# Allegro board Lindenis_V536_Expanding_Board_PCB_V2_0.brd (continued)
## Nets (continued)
MICIN1P: C52.2 U901.89(MICIN1P)
MICRO-USB0-DM: D25.1(ANODE) U51.6(HSD1-) USB1.2(D-)
MICRO-USB0-DP: D26.1(ANODE) U51.7(HSD1+) USB1.3(D+)
MIPI-DSI-CKN: J7.9(CLKN) TP56.1(TP) U901.143(MIPI_DSI_CKN)
MIPI-DSI-CKP: J7.8(CLKP) TP57.1(TP) U901.142(MIPI_DSI_CKP)
MIPI-DSI-D0N: J7.3(D0N) TP52.1(TP) U901.137(MIPI_DSI_D0N)
MIPI-DSI-D0P: J7.2(D0P) TP53.1(TP) U901.136(MIPI_DSI_D0P)
MIPI-DSI-D1N: J7.6(D1N) TP54.1(TP) U901.139(MIPI_DSI_D1N)
MIPI-DSI-D1P: J7.5(D1P) TP55.1(TP) U901.138(MIPI_DSI_D1P)
MIPI-DSI-D2N: J7.12(D2N) TP58.1(TP) U901.141(MIPI_DSI_D2N)
MIPI-DSI-D2P: J7.11(D2P) TP59.1(TP) U901.140(MIPI_DSI_D2P)
MIPI-DSI-D3N: J7.15(D3N) TP60.1(TP) U901.145(MIPI_DSI_D3N)
MIPI-DSI-D3P: J7.14(D3P) TP61.1(TP) U901.144(MIPI_DSI_D3P)
NALE-EMMC-RST: U901.77(EMMC_RST) UM2.12
NDQ0-EMMC-D7: U901.86(EMMC_D7) UM2.31
NDQ1-EMMC-D2: U901.84(EMMC_D2) UM2.27
NDQ2-EMMC-D6: U901.83(EMMC_D6) UM2.33
NDQ3-EMMC-D1: U901.81(EMMC_D1) UM2.29
NDQ4-EMMC-D5: U901.82(EMMC_D5) UM2.2
NDQ5-EMMC-D0: U901.85(EMMC_D0) UM2.6
NDQ6-EMMC-D4: U901.79(EMMC_D4) UM2.4
NDQ7-EMMC-D3: U901.80(EMMC_D3) UM2.10
NRB0-EMMC-CMD: U901.75(EMMC_CMD) UM2.25
NRE: RM50.2 UM2.8
NRE-EMMC-CLK: RM50.1 U901.76(EMMC_CLK)
NWE-EMMC-DS: U901.78(EMMC_DS) UM2.15
OVCUR1#: R237.2 R263.1 U32.21(OVCUR1#)
PA-SHDN: R182.2 U901.53(PA_SHDN)
PH4: J56.1 RU13.1 U901.56(PH4) UU3.4(EN)
PH10: J56.2 R549.2 U901.52(PH10)
PHYRST: CM14.1 Q23.3(D) RM21.1 RM45.2 UM1.12(PHYRSTB)
PHYRSTB: Q23.2(S) RM45.1 U901.16(RGMII_RESET)
PS: C291.2 C294.2 J11.2 J11.4 L12.1 U39.6(VIN) U901.35(PS1) U901.36(PS2)
PWKEY: CL67.1 DL52.2(CATHODE) QL13.3(C) U27.3(PWKEY)
PWR-LED: RL6.2 RL56.2 RL57.2 U901.55(LED_PWR)
PWRON: CK15.1 RP62.2 U901.7(PWRON)
REGOUT: CM17.2 LM1.1 RM42.2 UM1.30(REG_OUT)
RF-IN: RG3.1 U8.11(RF_IN)
RGMII-CLKIN-125M: R436.1 R541.1 U901.17(RGMII_CLKIN_125M)
RGMII-CLKIN-125M#: CM13.1 R541.2 RM14.2
RGMII-MDC: R442.1 R546.1 U901.23(RGMII_MDC)
RGMII-MDC#: R546.2 RM8.2
RGMII-MDIO: RM9.2 U901.26(RTGMII_MDIO)
RGMII-RXCK: R434.1 R537.1 U901.14(RGMII_RXCK)
RGMII-RXCK#: CM12.1 R537.2 RM13.2
RGMII-RXCTL: R435.1 R539.1 U901.15(RGMII_RXCTL)
RGMII-RXCTL#: R539.2 RM17.2
RGMII-RXD0: R433.1 R538.1 U901.13(RGMII_RXD0)
RGMII-RXD0#: R538.2 RM15.4(R4)
RGMII-RXD1: R432.1 R535.1 U901.12(RGMII_RXD1)
RGMII-RXD1#: R535.2 RM15.3(R3)
RGMII-RXD2: R431.1 R536.1 U901.11(RGMII_RXD2)
RGMII-RXD2#: R536.2 RM15.2(R2)
RGMII-RXD3: R430.1 R534.1 U901.10(RGMII_RXD3)
RGMII-RXD3#: R534.2 RM15.1(R1)
RGMII-TXCK: R441.1 R545.1 U901.18(RGMII_TXCK)
RGMII-TXCK#: R545.2 RM12.2
RGMII-TXCTL: R522.1 R547.1 U901.25(RGMII)TXCTL)
RGMII-TXCTL#: R547.2 RM54.2
RGMII-TXD0: R440.1 R544.1 U901.22(RGMII_TXD0)
RGMII-TXD0#: R544.2 RM5.1(R1)
RGMII-TXD1: R439.1 R543.1 U901.21(RGMII_TXD1)
RGMII-TXD1#: R543.2 RM5.2(R2)
RGMII-TXD2: R438.1 R542.1 U901.20(RGMII_TXD2)
RGMII-TXD2#: R542.2 RM5.3(R3)
RGMII-TXD3: R437.1 R540.1 U901.19(RGMII_TXD3)
RGMII-TXD3#: R540.2 RM5.4(R4)
RSET: R50.1 UM1.39(RSET)
RXC/PHYAD1: RM13.1 RM38.1 RM39.2 UM1.27(RXC/PHYAD1)
RXCTL/PHYAD2: RM17.1 RM40.1 RM41.2 UM1.26(RXCTL/PHYAD2)
RXD0/RXDLY: RM15.5(R5) RM24.1 RM25.2 UM1.25(RXD0/RXDLY)
RXD1/TXDLY: RM15.6(R6) RM22.1 RM23.2 UM1.24(RXD1/TXDLY)
RXD2/PLLOFF: RM15.7(R7) RM18.1 RM19.2 UM1.23(RXD2/PLLOFF)
RXD3/PHYAD0: RM15.8(R8) RM36.1 RM37.2 UM1.22(RXD3/PHYAD0)
S-TWI1-SCK: J35.3 R77.1 U901.119(S_TWI1_SCK) U902.12(SCX)
S-TWI1-SDA: J35.4 R78.1 U901.118(S_TWI1_SDA) U902.2(SDI)
SDC0-CLK: D11.1(ANODE) J3.5(CLK) U901.100(SDC0_CLK)
SDC0-CMD: D12.1(ANODE) J3.3(CMD) U901.101(SDC0_CMD)
SDC0-D0: D15.1(ANODE) J3.7(DAT0) U901.99(SDC0_D0)
SDC0-D1: D16.1(ANODE) J3.8(DAT1) U901.98(SDC0_D1)
SDC0-D2: D14.1(ANODE) J3.1(DAT2) U901.103(SDC0_D2)
SDC0-D3: D13.1(ANODE) J3.2(DAT3) RC9.1 U901.102(SDC0_D3)
SDC0-DET: R401.2 U901.104(SDC0_DET)
TS: J1.2 U901.29(TS)
TWI1-SCK: J36.3 JL6.6(CTP-SCL) R41.2 R75.1 R531.1 U11.2 U901.5(TWI1_SCK)
TWI1-SDA: J36.4 JL6.5(CTP-SDA) R40.2 R76.1 R532.1 U11.1 U901.6(TWI1_SDA)
TXC: CM11.1 RM12.1 UM1.20(TXC)
TXCTL: RM54.1 UM1.19(TXCTL)
TXD0: RM5.8(R8) UM1.18(TXD0)
TXD1: RM5.7(R7) UM1.17(TXD1)
TXD2: RM5.6(R6) UM1.16(TXD2)
TXD3: RM5.5(R5) UM1.15(TXD3)
UART4_RX: Q2.2(S) R13.1 RG1.1 RG4.1 U901.4(UART4_RX)
UART4_TX: R348.2 RG2.1 RG5.1 U901.3(UART4_TX)
USB1-DM: U51.4(D-) U901.49(USB1_DM)
USB1-DP: U51.3(D+) U901.48(USB1_DP)
USB1_DM: U32.25(DM0) U51.8(HSD2-)
USB1_DP: U32.26(DP0) U51.9(HSD2+)
USB-SEL: R419.1 U51.2(SEL)
USB_RESET: C218.2 R229.1 R238.2 U32.13(\\R\E\S\E\T)
USBVBUS: C185.2 C186.2 C192.2 C193.2 J9.4(VBUS4) J9.8(VUSB2) RU12.2 U27.11(USB_VBUS) UU3.1(OUT)
USIM_CLK: CL29.1 RL25.1 U27.19(USIM_CLK)
USIM_DATA: CW30.1 RL40.2 U27.17(USIM_DATA)
USIM_RST: CL28.1 RL24.1 U27.18(USIM_RST)
USIM_VDD: CL31.1 CL32.1 JL26.C6(VPP) RL41.1 TP83.1(TP) U27.20(USIM_VDD)
V-BAT: CL46.2 CL48.2 CL80.2 CL81.2 CL82.2 CL86.2 OC5.1 OC6.1 RL45.1 U27.62(VBAT3) U27.63(VBAT4)
VLED+: C293.2 C295.2 D41.2 J7.35(A1) J7.36(A2) TP67.1(TP) U39.5(VOUT)
VLED-: J7.28(K1) J7.29(K2) R315.1 R318.2 TP64.1(TP)
WL-PMU-EN: R527.2 U12.9(WL-REG-ON) U901.154(WL_PMU_EN)
WL-SDIO-CLK: U12.3(CLK) U901.150(WL_SDIO_CLK)
WL-SDIO-CMD: U12.7(CMD) U901.151(WL_SDIO_CMD)
WL-SDIO-D0: U12.2(D0) U901.149(WL_SDIO_D0)
WL-SDIO-D1: U12.4(D1) U901.148(WL_SDIO_D1)
WL-SDIO-D2: U12.6(D2) U901.153(WL_SDIO_D2)
WL-SDIO-D3: U12.8(D3) U901.152(WL_SDIO_D3)
WL-WAKE-AP: U12.11(WL-WAKE-AP) U901.106(WL_WAKE_AP)
X1: C338.1 U32.6(X1) Y3.1
X32KFOUT: U12.10(AP-CK32) U901.147(X32KFOUT)
XI2: C230.2 U32.7(X2) Y3.3
XTAL-IN: C139.2 UM1.36(XTAL_IN) X3.1(XIN)
XTAL-OUT: R51.2 RM56.1 UM1.37(XTAL_OUT/EXT_CLK)
N17770502: CW27.1 RL20.1 RL23.2
N17770537: CW26.1 RL20.2 U27.82(MAIN_ANT)
N17770634: ANT2.3 RL23.1
N17772040: DL51.2(CATHODE) JL26.C7(I/O) RL40.1 TP84.1(TP)
N17772586: JL26.C1(VCC) RL41.2 TP79.1(TP)
N17773525: CL94.1 RL38.1 UL9.4(EN)
N17773548: CL64.2 RL39.2 RL84.2 UL9.3(FB)
N17773558: CL61.1 CL62.1 CL64.1 CL66.1 CL69.1 LP7.2 RL45.2 RL84.1
N17773576: CL88.2 LP7.1 UL9.6(LX)
N17773604: CL88.1 UL9.1(BS)
N17784951: QL13.1(B) RL69.1 RL70.1
N17956748: DL49.2(CATHODE) JL26.C2(RST) RL24.2 TP80.1(TP)
N17956763: DL50.2(CATHODE) JL26.C3(CLK) RL25.2 TP81.1(TP)
N19642444: C275.2 J3.4(VDD) RC1.2
N19809825: J3.9(CD#) R401.1
N19810892: C56.2 R19.1 R20.1
N19810945: C56.1 R23.1 R24.1
N19811956: D39.2(CATHODE) J21.2(B) R422.2
N19811968: D40.2(CATHODE) J21.4(D) R33.2
N19812150: C384.2 R422.1 R423.1
N19812152: C75.2 R33.1 R421.1
N19829872: KK1.4(6) RK2.1 RK3.2
N19829876: KK2.4(6) RK3.1 RK4.2
N19829887: KK3.4(6) RK4.1 RK5.2
N19829903: KK4.4(6) RK5.1 RK6.2
N19829909: KK5.4(6) RK6.1
N19829940: KP1.4 RP62.1
N19829965: KK6.4(6) RK7.1
N19833462: DH12.2 RH16.1
N19840129: QL5.3(C) RL49.1
N19841860: R45.1 R46.2 U2.4(FB)
N19841911: D7.1 R39.2
N19843250: CG2.2 RG3.2 RG6.1
N19843374: RG4.2 U8.20(TXD0)
N19843376: RG5.2 U8.21(RXD0)
N19843437: ANT3.3(CENTER1) CG3.2 RG6.2
N19850791: R239.2 U32.4(PREF)
N19866924: DL6.2(CATHODE) RL1.2
N19866926: QL1.3(C) RL4.2 RL56.1
N19866930: QL3.3(C) RL1.1 RL13.1
N19866943: QL1.1(B) RL6.1 RL85.1
N19866974: QL3.1(B) RL14.1 RL15.1
N19867123: DL7.2(CATHODE) RL4.1
N19875396: R316.2 R318.1 U39.3(FB)
N19875466: C292.2 R316.1 R319.2
N19875497: D41.1 L12.2 U39.1(LX)
N19896949: DM1.1(ANODE) RM28.1 RM34.2
N19896956: DM1.2(CATHODE) RM33.1 RM35.1
N19897306: CM18.2 CM19.1 LM1.2 RM42.1 RM43.2 RM44.2
N19897342: C140.2 R51.1 X3.3(XOUT)
N19898869: C206.1 U19.1(VCC)
N19898879: RM55.2 U19.13(Y-)
N19898907: RM2.2 U19.12(G-)
N19916216: J12.5 R348.1
N19916242: J12.4 Q2.3(D)
N19933444: J80.2 R292.2 R419.2 R420.1
N19963769: C189.1 U23.4(PVSS)
N19963781: R177.2 R179.1 U23.10(INTR)
N19963785: C470.2 R177.1
N19963787: R179.2 R181.2 U23.9(OUTR)
N19963809: R183.2 R184.2 U23.8(UVP)
N19963840: R174.1 R178.1 U23.1(-INL)
N19963846: R178.2 R180.1 U23.2(OUTL)
N19963852: C183.1 R174.2
N19963856: R182.1 R185.1 U23.3(EN)
N19963865: C468.2 U23.6(CP)
N19963871: C468.1 U23.5(CN)
N19965778: RU14.1 UU3.3(ISET)
N19978083: J81.1(IN) R548.2
N19984458: R549.1 R550.2 USB1.4(ID)
N22541145: DH2.1(ANODE) JH1.19(HOT_PLUG_DET) RH5.2
N198287081: R192.2 U902.11(PS)
N198400281: QL5.1(B) RL48.2
N198419350: R43.1 U2.3(EN)
N199505671: R269.1 U24.3(EN)

Pads without a net: J7 20 21 22 23 25 26 31 34 40; J12 3; J21 1 3; J79 1 3; JH1 14; KK1 1 3; KK2 1 3; KK3 1 3; KK4 1 3; KK5 1 3; KK6 1 3; KP1 1 3; U8 1 2 3 4 5 6 14 15 16 17 18 19; U11 11; U13 1 3 5 7; U24 4; U27 4 6 7 8 9 16 21 22 23 24 25 26 27 28 29 30 31 32 33 34 35 36 38 39 42 44 45 46 47 48 50 51 52 53 54 55 56 59 66 67 68 69 70 71 73 74 75 76 79 83 84 85 86 87; U32 14 17 18 19 20 22 23; U902 1 5 6 10; UM2 13 16 17 18 19

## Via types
v1: diameter 0.406, hole 0.203, TOP to BOTTOM, 1857 vias
v2: diameter 0.61, hole 0.305, TOP to BOTTOM, 97 vias

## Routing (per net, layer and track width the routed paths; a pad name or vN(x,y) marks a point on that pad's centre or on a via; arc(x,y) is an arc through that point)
3V3-STBY: length 6.4
  TOP w0.508: RP75.1 103.57,61.98 U8.23 ; RP75.1 RP84.1 ; RP75.1 103.26,63.08 U8.22
AVDD1: length 34.1
  TOP w0.254: U32.1 29.85,44.06 29.46,44.45 29.46,47.24 v1(27.69,49.02) ; 29.34,38.21 U32.10 ; v1(27.69,45.47) 27.84,45.31 27.84,42.77 29.15,41.46 U32.5
  TOP w0.406: v1(27.69,45.47) C231.2 C332.2 ; 29.34,38.21 27.87,38.21 C330.2 C333.2 27.94,39.24 v1(28.32,38.86) ; C217.2 v1(27.69,49.02)
  TOP w0.508: R241.1 v2(28.45,34.8)
  BOTTOM w0.406: v1(27.69,49.02) v1(27.69,45.47) 28.32,44.83 v1(28.32,38.86) 28.32,34.92 v2(28.45,34.8)
AVDD10: length 17
  TOP w0.203: UM1.8 22.12,62.46 22.1,62.48 v1(22,62.48) ; UM1.3 22.03,64.46 v1(21.97,64.52) ; v2(24,66.67) 24,66.67 UM1.38
  TOP w0.508: v2(36.47,65.87) 36.91,66.31 RM44.1
  BOTTOM w0.406: CM20.1 22.58,63.91 22.29,64.2 22.28,64.2 22.1,64.38 22.1,64.39 v1(21.97,64.52)
  BOTTOM w0.508: v2(24,66.67) 24.38,66.29 28.7,66.29 29.08,66.67 35.76,66.67 36.47,65.96 v2(36.47,65.87)
AVDD33: length 18.1
  TOP w0.203: UM1.40 22.68,65.84 22.35,66.17
  TOP w0.254: v1(22.35,60.33) 22.61,60.33 23.2,60.92 UM1.11
  TOP w0.508: 22.35,66.17 21.38,67.14 CM27.2 CM28.2 21.38,69.73 RM4.1 v2(22.17,69.78)
  BOTTOM w0.406: v2(22.17,69.78) 20.74,68.35 20.74,64.18 21.49,63.43 21.49,60.71 21.87,60.33 v1(22.35,60.33)
DVDD10: length 17.7
  TOP w0.254: CM16.1 29.46,59.25 v1(29.46,60.02) 29.26,60.02 27.62,61.66 UM1.21
  TOP w0.508: RM43.1 37.72,66.27 37.72,62.33 v2(37.85,62.2)
  BOTTOM w0.508: v1(29.46,60.02) 29.46,60.63 30.51,61.67 33.6,61.67 34.26,62.33 37.62,62.33 37.74,62.2 v2(37.85,62.2)
DVDD33: length 34.8
  TOP w0.203: 28.45,64.86 UM1.29
  TOP w0.254: RM27.1 RM20.2 31.86,70.83 v1(31.88,70.84)
  TOP w0.406: RM53.1 34.94,64.23 34.37,64.23 RM52.1 34.02,64.58 CM9.2 30.79,64.56 CM8.2 29.17,64.56 v1(28.83,64.9) 28.79,64.86 28.45,64.86 ; RM34.1 31.89,72.12 v1(31.88,72.14)
  L2GND w0.406: v1(28.83,64.9) 28.83,71.7 28.93,71.8 28.93,72.42 v1(28.45,72.9)
  BOTTOM w0.381: v1(28.83,64.9) 25.22,61.29 24,61.29 22.85,60.13 22.85,60.12 22.5,59.77 22.5,59.2 21.78,58.48
  BOTTOM w0.406: v1(28.45,72.9) 29.01,72.9 RM32.1 RM30.1 31.46,72.92 31.88,72.51 v1(31.88,72.14) v1(31.88,70.84) ; RM21.2 21.78,58.48
DVDDRG: length 26.7
  TOP w0.203: UM1.28 28.13,64.46 28.45,64.14
  TOP w0.254: RM16.2 24.34,58.55 28.07,58.55 v1(28.32,58.8) ; RM7.1 36.09,62.51 36.09,61.57 36.83,60.83 36.83,59.69 36,58.86 v1(35.19,58.86)
  TOP w0.406: RM7.1 35.02,63.58 RM52.2 32.68,63.58 CM7.2 CM10.2 CM25.2 CM26.2 29.04,63.54 28.45,64.14
  BOTTOM w0.254: v1(35.19,58.86) 35.19,58.9 34.78,59.31 RM39.1 RM41.1 RM25.1 RM23.1 RM19.1 RM37.1 29.57,58.8 v1(28.32,58.8)
GND: length 974.9
  TOP w0.25: R50.2 22.48,68.8 ; R50.2 22.05,68.37 ; R50.2 22.91,68.37 ; 23.02,69.41 C140.1 ; C140.1 23.45,69.84 ; C140.1 23.45,68.98 ; 26.21,69.84 C139.1 26.21,68.98 ; 29.85,58.35 CM16.2 29.42,57.93 ; 21.54,58.05 CM14.2 ; CM14.2 21.97,58.48 ; CM14.2 21.12,58.48
  TOP w0.254: UM2.9 36.52,16.7 v1(36.58,16.64) ; v1(122.83,39.58) 122.85,39.56 J7.13 ; D25.2 8.08,16.81 v1(8.13,16.76) ; CM17.1 28.92,67.48 v1(28.29,66.85) ; v1(37.34,19.56) 37.68,19.9 UM2.34 ; CM13.2 26.68,67.63 v1(26.87,67.82) ; D26.2 v1(8.08,14.05) ; JH1.5 v1(116.93,8.68) ; v1(33.23,62.69) CM7.1 CM10.1 CM25.1 CM26.1 ; DH5.2 v1(110.36,15.24) ; v1(122.88,38.05) 122.88,38.06 J7.10 ; CM16.2 28.89,58.35 28.83,58.42 28.83,58.67 ; UM2.11 36.55,15.9 v1(36.58,15.88) ; v1(36.58,14.61) 36.48,14.7 UM2.14 ; UM2.28 v1(37.37,17.5) ; v1(96.21,24.89) U901.122 v1(94.11,24.89) ; v1(36.58,17.53) 36.55,17.5 UM2.7 ; JH1.2 v1(118.43,8.7) ; DH3.2 DH4.2 109.47,15.11 109.52,15.16 v1(109.52,15.24) ; CM15.1 28.24,70.82 v1(28.19,70.87) ; UM2.24 v1(37.36,15.9) ; UM2.32 37.39,19.1 v1(37.34,19.05) ; v1(26.8,68.96) 26.35,69.41 C139.1 ; JH1.17 v1(110.93,12.14) ; Y3.4 25.82,44.16 v1(25.02,44.96) ; v1(118.13,12.97) UH1.8 UH1.3 v1(118.13,15.35) ; v1(26.71,69.83) 26.69,69.85 26.69,70 X3.4 ; DH2.2 v1(106.81,15.24) ; UM2.30 v1(37.35,18.3) ; v1(114.7,12.97) UH2.8 UH2.3 v1(114.7,15.35) ; JH1.11 v1(113.93,8.64) ; C230.1 v1(27.18,40.79) ; C182.1 v2(8.43,17.32) ; CH2.2 v1(107.7,15.24) ; JH1.8 v1(115.43,8.65) ; UM2.5 v1(36.57,18.3) ; UM2.26 v1(37.4,16.7) ; UM2.3 v1(36.62,19.1)
  TOP w0.406: CL66.2 v1(116.33,39.37) ; RM38.2 34.78,59.16 v1(34.54,58.93) ; RM40.2 33.89,58.95 v1(33.91,58.93) ; v1(21.21,57.78) 21.21,58.15 CM14.2 ; CL62.2 v1(114.81,39.93) ; RM36.2 v1(30.33,58.95) ; RM18.2 v1(31.22,58.95) ; CL61.2 v1(117.47,38.61) ; RL39.1 104.69,41.87 v1(104.65,41.83) 104.77,41.7 UL9.2 ; RM24.2 v1(33,58.95) ; CL69.2 v1(112.9,39.93) ; RM22.2 v1(32.11,58.95)
  TOP w0.508: JH1.21 121.68,11.49 ; JH1.21 122.61,9.66 ; JH1.21 121.68,7.83 ; JH1.21 120.75,9.66 ; 56.4,82.68 J36.1 ; J36.1 58.41,82.68 ; J36.1 57.4,83.68 ; 107.18,7.83 JH1.20 ; JH1.20 108.11,9.66 ; JH1.20 106.25,9.66 ; JH1.20 107.18,11.49 ; U11.10 90.42,78.53 ; U11.10 89.5,77.6 ; U11.10 91.35,77.6 ; U11.10 90.42,76.67 ; 12.96,5.26 J81.3 ; J81.3 12.96,7.62 ; J81.3 13.89,6.44 ; J81.3 12.03,6.44 ; 72.11,75.33 U22.19 70.51,75.33 ; JH1.23 121.68,5.03 ; JH1.23 122.61,3.7 ; JH1.23 120.75,3.7 ; JH1.23 121.68,2.37 ; 62.12,82.68 J56.3 ; J56.3 64.12,82.68 ; J56.3 63.12,83.68 ; J11.12 28.36,78.23 ; J11.12 27.43,79.16 ; J11.12 26.5,78.23 ; 107.18,2.37 JH1.22 ; JH1.22 108.11,3.7 ; JH1.22 106.25,3.7 ; JH1.22 107.18,5.03 ; 24.81,28.96 U12.1 ; U12.1 26.47,28.96 ; U12.1 25.64,29.79 ; U12.1 25.64,28.14 ; 13.15,32.83 J9.1 ; J9.1 12.27,33.71 ; J9.1 14.03,33.71 ; J12.2 109.31,82.84 ; J12.2 108.38,81.91 ; J12.2 109.31,80.98 ; J12.2 110.24,81.91 ; J9.11 7.82,45.81 ; J9.11 5.79,43.78 ; J9.11 7.82,41.75 ; J9.11 9.85,43.78 ; 8.97,53.41 U19.16 ; U19.16 10.65,55.09 ; U19.16 12.33,53.41 ; U19.16 10.65,51.73 ; 11.56,42.96 J9.9 ; J9.9 13.5,45.81 ; J9.9 12.01,45.27 ; J9.9 12.68,45.72 ; J9.9 12.01,42.3 ; J9.9 15.43,44.6 ; J9.9 14.32,45.72 ; J9.9 11.47,43.78 ; J9.9 14.98,45.27 ; J9.9 15.53,43.78 ; J9.9 11.56,44.6 ; 5.79,30.64 J9.12 ; J9.12 7.82,32.67 ; J9.12 9.85,30.64 ; 38.82,5.46 39.75,5.46 ; 39.75,5.46 39.75,6.39 ; 39.75,5.46 39.75,4.53 ; 39.75,5.46 40.68,5.46 ; 24.89,79.16 J11.14 25.82,78.23 ; 8.97,68.9 U19.15 ; U19.15 10.65,70.58 ; U19.15 12.33,68.9 ; U19.15 10.65,67.22 ; J1.3 3.84,75.18 ; J1.3 3.84,73.53 ; J1.3 3.01,74.35 ; J1.3 4.67,74.35 ; 89.5,75.06 U11.9 ; U11.9 91.35,75.06 ; U11.9 90.42,75.99 ; 29.64,29.79 U12.5 29.64,28.14 ; J12.1 111.81,82.84 ; J12.1 112.74,81.91 ; J12.1 111.81,80.98 ; J12.1 110.88,81.91 ; J9.5 10.44,34.59 ; J9.5 10.44,32.83 ; J9.5 11.32,33.71 ; J9.5 9.56,33.71 ; U13.9 31.63,53.76 ; U13.9 32.46,52.93 ; U13.9 30.8,52.93 ; U13.9 31.63,52.1 ; J33.3 74.92,82.68 ; J33.3 73.91,83.68 ; J33.3 72.91,82.68 ; J11.13 24.89,81.7 ; J11.13 24.89,79.84 ; J11.13 23.96,80.77 ; J11.13 25.82,80.77 ; 39.75,1.99 39.75,2.92 ; 39.75,2.92 38.82,2.92 ; 39.75,2.92 40.68,2.92 ; 39.75,2.92 39.75,3.85 ; 96.43,75.06 U11.13 94.58,75.06 ; 29.97,79.84 J11.9 ; J11.9 29.97,81.7 ; J11.9 29.04,80.77 ; 36.47,30.96 U12.12 35.64,30.14 ; U19.10 13.95,56.63 ; U19.10 12.77,55.45 ; U19.10 15.13,55.45 ; U19.10 13.95,54.27 ; J11.11 28.36,80.77 ; J11.11 27.43,79.84 ; J11.11 27.43,81.7 ; J11.11 26.5,80.77 ; 36.8,54.93 U13.16 ; U13.16 37.63,54.1 ; U13.16 37.63,55.76 ; U13.16 38.46,54.93 ; 8.98,4.14 J81.2 ; J81.2 10.16,3.21 ; J81.2 11.34,4.14 ; J81.2 10.16,5.07 ; 30.8,54.93 U13.10 ; U13.10 32.46,54.93 ; U13.10 31.63,55.76 ; U13.10 31.63,54.1 ; 17.27,79.84 J11.19 ; J11.19 18.2,80.77 ; J11.19 17.27,81.7 ; J11.19 16.34,80.77 ; 91.45,82.68 J35.1 ; J35.1 93.46,82.68 ; J35.1 92.46,83.68 ; 29.04,78.23 J11.10 29.97,79.16 ; 81.88,75.06 U11.3 83.73,75.06 ; 11.47,30.64 J9.10 ; J9.10 15.53,30.64 ; J9.10 13.5,32.67 ; 37.63,52.1 U13.15 ; U13.15 38.46,52.93 ; U13.15 37.63,53.76 ; U13.15 36.8,52.93
  L2GND w0.508: J12.1 111.81,82.84 ; J12.1 111.81,80.98 ; J12.1 112.74,81.91 ; J12.1 110.88,81.91 ; 38.82,5.46 39.75,5.46 ; 39.75,5.46 39.75,6.39 ; 39.75,5.46 40.68,5.46 ; 39.75,5.46 39.75,4.53 ; J56.3 63.12,83.68 ; J56.3 63.12,81.67 ; J56.3 64.12,82.68 ; J56.3 62.12,82.68 ; 12.96,5.26 J81.3 ; J81.3 13.89,6.44 ; J81.3 12.96,7.62 ; J81.3 12.03,6.44 ; 30.8,54.93 U13.10 ; U13.10 31.63,55.76 ; U13.10 31.63,54.1 ; U13.10 32.46,54.93 ; J81.2 10.16,5.07 ; J81.2 8.98,4.14 ; J81.2 11.34,4.14 ; J81.2 10.16,3.21 ; 11.47,43.78 J9.9 ; J9.9 13.5,45.81 ; J9.9 15.53,43.78 ; J9.9 13.5,41.75 ; 8.97,53.41 U19.16 ; U19.16 10.65,55.09 ; U19.16 10.65,51.73 ; U19.16 12.33,53.41 ; U11.9 90.42,75.99 ; U11.9 90.42,74.13 ; U11.9 91.35,75.06 ; U11.9 89.5,75.06 ; J36.1 57.4,83.68 ; J36.1 58.41,82.68 ; J36.1 56.4,82.68 ; J36.1 57.4,81.67 ; 27.43,77.3 J11.12 ; J11.12 26.5,78.23 ; J11.12 27.43,79.16 ; J11.12 28.36,78.23 ; J11.13 25.82,80.77 ; J11.13 24.89,81.7 ; J11.13 24.89,79.84 ; J11.13 23.96,80.77 ; 39.75,1.99 39.75,2.92 ; 39.75,2.92 40.68,2.92 ; 39.75,2.92 39.75,3.85 ; 39.75,2.92 38.82,2.92 ; JH1.20 107.18,11.49 ; JH1.20 107.18,7.83 ; JH1.20 108.11,9.66 ; JH1.20 106.25,9.66 ; 13.15,32.83 J9.1 ; J9.1 14.03,33.71 ; J9.1 13.15,34.59 ; J9.1 12.27,33.71 ; 90.42,76.67 U11.10 ; U11.10 89.5,77.6 ; U11.10 91.35,77.6 ; U11.10 90.42,78.53 ; JH1.23 121.68,5.03 ; JH1.23 120.75,3.7 ; JH1.23 122.61,3.7 ; JH1.23 121.68,2.37 ; U12.1 25.64,29.79 ; U12.1 24.81,28.96 ; U12.1 26.47,28.96 ; U12.1 25.64,28.14 ; 94.58,75.06 U11.13 ; U11.13 96.43,75.06 ; U11.13 95.5,75.99 ; U11.13 95.5,74.13 ; J11.19 17.27,81.7 ; J11.19 18.2,80.77 ; J11.19 16.34,80.77 ; J11.19 17.27,79.84 ; 37.63,52.1 U13.15 ; U13.15 38.46,52.93 ; U13.15 36.8,52.93 ; U13.15 37.63,53.76 ; U12.5 29.64,29.79 ; U12.5 29.64,28.14 ; U12.5 30.47,28.96 ; U12.5 28.81,28.96 ; 72.91,82.68 J33.3 ; J33.3 74.92,82.68 ; J33.3 73.91,83.68 ; J33.3 73.91,81.67 ; 108.38,81.91 J12.2 ; J12.2 109.31,80.98 ; J12.2 110.24,81.91 ; J12.2 109.31,82.84 ; J1.3 4.67,74.35 ; J1.3 3.84,75.18 ; J1.3 3.84,73.53 ; J1.3 3.01,74.35 ; 107.18,2.37 JH1.22 ; JH1.22 108.11,3.7 ; JH1.22 106.25,3.7 ; JH1.22 107.18,5.03 ; 27.43,79.84 J11.11 ; J11.11 28.36,80.77 ; J11.11 26.5,80.77 ; J11.11 27.43,81.7 ; 31.63,52.1 U13.9 ; U13.9 32.46,52.93 ; U13.9 31.63,53.76 ; U13.9 30.8,52.93 ; 35.64,30.14 U12.12 ; U12.12 35.64,31.79 ; U12.12 36.47,30.96 ; U12.12 34.81,30.96 ; U19.15 10.65,70.58 ; U19.15 10.65,67.22 ; U19.15 8.97,68.9 ; U19.15 12.33,68.9 ; 29.97,77.3 J11.10 ; J11.10 29.97,79.16 ; J11.10 30.9,78.23 ; J11.10 29.04,78.23 ; J11.9 30.9,80.77 ; J11.9 29.04,80.77 ; J11.9 29.97,81.7 ; J11.9 29.97,79.84 ; 70.51,77.33 U22.20 ; U22.20 72.11,77.33 ; U22.20 71.31,78.13 ; U22.20 71.31,76.53 ; 13.5,28.61 J9.10 ; J9.10 11.47,30.64 ; J9.10 15.53,30.64 ; J9.10 13.5,32.67 ; 92.46,81.67 J35.1 ; J35.1 91.45,82.68 ; J35.1 92.46,83.68 ; J35.1 93.46,82.68 ; U13.16 38.46,54.93 ; U13.16 37.63,55.76 ; U13.16 36.8,54.93 ; U13.16 37.63,54.1 ; JH1.21 122.61,9.66 ; JH1.21 121.68,11.49 ; JH1.21 120.75,9.66 ; JH1.21 121.68,7.83 ; J9.11 7.82,45.81 ; J9.11 5.79,43.78 ; J9.11 7.82,41.75 ; J9.11 9.85,43.78 ; 12.77,55.45 U19.10 ; U19.10 13.95,56.63 ; U19.10 13.95,54.27 ; U19.10 15.13,55.45 ; 10.44,32.83 J9.5 ; J9.5 10.44,34.59 ; J9.5 11.32,33.71 ; J9.5 9.56,33.71 ; U11.3 82.8,75.99 ; U11.3 83.73,75.06 ; U11.3 82.8,74.13 ; U11.3 81.88,75.06 ; J9.12 9.85,30.64 ; J9.12 7.82,28.61 ; J9.12 5.79,30.64 ; J9.12 7.82,32.67 ; 23.96,78.23 J11.14 ; J11.14 24.89,79.16 ; J11.14 24.89,77.3 ; J11.14 25.82,78.23 ; 71.31,74.53 U22.19 ; U22.19 71.31,76.13 ; U22.19 72.11,75.33 ; U22.19 70.51,75.33
  L3SIG w0.508: U19.15 12.33,68.9 ; U19.15 10.65,70.58 ; U19.15 8.97,68.9 ; U19.15 10.65,67.22 ; U22.19 71.31,76.13 ; U22.19 70.51,75.33 ; U22.19 71.31,74.53 ; U22.19 72.11,75.33 ; 17.27,79.84 J11.19 ; J11.19 17.27,81.7 ; J11.19 16.34,80.77 ; J11.19 18.2,80.77 ; 26.5,80.77 J11.11 ; J11.11 27.43,81.7 ; J11.11 28.36,80.77 ; J11.11 27.43,79.84 ; J81.2 11.34,4.14 ; J81.2 10.16,5.07 ; J81.2 10.16,3.21 ; J81.2 8.98,4.14 ; 72.91,82.68 J33.3 ; J33.3 73.91,83.68 ; J33.3 73.91,81.67 ; J33.3 74.92,82.68 ; J1.3 3.84,75.18 ; J1.3 3.84,73.53 ; J1.3 4.67,74.35 ; J1.3 3.01,74.35 ; 11.47,30.64 J9.10 ; J9.10 13.5,32.67 ; J9.10 13.5,28.61 ; J9.10 15.53,30.64 ; U22.20 71.31,78.13 ; U22.20 71.31,76.53 ; U22.20 72.11,77.33 ; U22.20 70.51,77.33 ; 39.75,5.46 40.68,5.46 ; 39.75,5.46 39.75,6.39 ; 39.75,5.46 38.82,5.46 ; 39.75,5.46 39.75,4.53 ; U19.16 10.65,55.09 ; U19.16 8.97,53.41 ; U19.16 12.33,53.41 ; U19.16 10.65,51.73 ; 12.27,33.71 J9.1 ; J9.1 13.15,32.83 ; J9.1 13.15,34.59 ; J9.1 14.03,33.71 ; J81.3 13.89,6.44 ; J81.3 12.96,7.62 ; J81.3 12.96,5.26 ; J81.3 12.03,6.44 ; 121.68,7.83 JH1.21 ; JH1.21 121.68,11.49 ; JH1.21 122.61,9.66 ; JH1.21 120.75,9.66 ; 7.82,28.61 J9.12 ; J9.12 7.82,32.67 ; J9.12 5.79,30.64 ; J9.12 9.85,30.64 ; 29.04,78.23 J11.10 ; J11.10 30.9,78.23 ; J11.10 29.97,77.3 ; J11.10 29.97,79.16 ; U11.3 82.8,75.99 ; U11.3 81.88,75.06 ; U11.3 82.8,74.13 ; U11.3 83.73,75.06 ; J11.13 24.89,81.7 ; J11.13 25.82,80.77 ; J11.13 23.96,80.77 ; J11.13 24.89,79.84 ; 10.44,32.83 J9.5 ; J9.5 11.32,33.71 ; J9.5 10.44,34.59 ; J9.5 9.56,33.71 ; J9.11 9.85,43.78 ; J9.11 5.79,43.78 ; J9.11 7.82,41.75 ; J9.11 7.82,45.81 ; J11.14 25.82,78.23 ; J11.14 24.89,79.16 ; J11.14 24.89,77.3 ; J11.14 23.96,78.23 ; 96.43,75.06 U11.13 95.5,74.13 ; J12.1 112.74,81.91 ; J12.1 111.81,82.84 ; J12.1 110.88,81.91 ; J12.1 111.81,80.98 ; 26.5,78.23 J11.12 ; J11.12 27.43,77.3 ; J11.12 28.36,78.23 ; J11.12 27.43,79.16 ; 39.75,2.92 39.75,3.85 ; 39.75,2.92 38.82,2.92 ; 39.75,2.92 40.68,2.92 ; 39.75,2.92 39.75,1.99 ; JH1.22 108.11,3.7 ; JH1.22 107.18,2.37 ; JH1.22 106.25,3.7 ; JH1.22 107.18,5.03 ; 63.12,81.67 J56.3 ; J56.3 63.12,83.68 ; J56.3 62.12,82.68 ; J56.3 64.12,82.68 ; 13.95,54.27 U19.10 ; U19.10 13.95,56.63 ; U19.10 15.13,55.45 ; U19.10 12.77,55.45 ; JH1.20 107.18,11.49 ; JH1.20 108.11,9.66 ; JH1.20 106.25,9.66 ; JH1.20 107.18,7.83 ; J35.1 92.46,83.68 ; J35.1 93.46,82.68 ; J35.1 91.45,82.68 ; J35.1 92.46,81.67 ; 89.72,78.3 U11.10 89.51,77.99 ; J36.1 57.4,83.68 ; J36.1 57.4,81.67 ; J36.1 56.4,82.68 ; J36.1 58.41,82.68 ; 108.38,81.91 J12.2 ; J12.2 110.24,81.91 ; J12.2 109.31,80.98 ; J12.2 109.31,82.84 ; 121.68,2.37 JH1.23 ; JH1.23 120.75,3.7 ; JH1.23 121.68,5.03 ; JH1.23 122.61,3.7 ; J9.9 13.5,45.81 ; J9.9 11.47,43.78 ; J9.9 15.53,43.78 ; J9.9 13.5,41.75 ; J11.9 30.9,80.77 ; J11.9 29.97,79.84 ; J11.9 29.04,80.77 ; J11.9 29.97,81.7
  BOTTOM w0.127: v1(46.24,66.27) v1(44.07,66.27) 43.62,66.27 42.75,65.4 40.25,65.4 v1(39.12,64.26) ; v1(44.2,65.56) 43.59,65.56 42.95,64.91 41.02,64.91 ; v1(61.21,66.27) 63.35,66.27 ; v1(42.11,67.62) 41.89,67.4 38.82,67.4 v1(38.73,67.31)
  BOTTOM w0.25: D11.2 92.12,17.06 ; D11.2 91.27,17.06 ; D11.2 91.69,17.49 ; 36.24,60.37 CM12.2 35.81,60.8 ; 31.47,70.22 RM26.2 30.61,70.22 ; 22.18,61.42 CM21.2 ; CM21.2 22.61,61 ; CM21.2 23.03,61.42 ; 23.12,65.3 CM22.2 22.69,65.73 ; RM2.1 4.18,70.92 ; RM2.1 3.75,71.35 ; RM2.1 3.75,70.49 ; 23.09,65.19 CM20.2 23.09,64.76
  BOTTOM w0.254: v1(111.6,19.91) 111.63,19.94 CL32.2 ; DL49.1 111.63,21.72 v1(111.43,21.52) ; v1(61.87,70) 61.71,70 60.33,68.63 43.12,68.63 v1(42.11,67.62) ; v1(61.21,66.27) v1(57.66,66.27) v1(46.24,66.27) ; v1(89.03,81.92) 88.65,81.53 C457.1 ; 73.91,67.44 74.55,68.07 CM11.2 ; v1(110.13,17.57) 110.45,17.25 CL29.2 ; RM26.2 v1(31.04,70.82) ; v1(88.27,81.92) 87.5,81.15 C458.1 ; DL51.1 114.41,16 v1(114.54,15.87) ; v1(76.45,62.51) v1(74.04,62.51) v1(67.16,62.51) v1(62.28,62.51) v1(57.28,62.51) 44.22,62.51 v1(43.81,62.1) ; CL31.2 111.25,19.05 v1(111.12,18.92) ; v1(109.6,20.45) 109.98,20.83 CL28.2 ; v1(61.24,70.56) 61.24,70.48 60.17,69.41 42.94,69.41 41.57,68.04 v1(41.53,68.04) 41.51,68.02 v1(39.37,68.02) v1(38.1,68.02) v1(37.34,68.02) v1(36.45,68.02) ; DL50.1 v1(111.25,17.91)
  BOTTOM w0.354: C89.1 45.81,6.99 ; C89.1 45.38,6.56 ; C89.1 45.38,7.41
  BOTTOM w0.406: CM22.2 v1(23.12,66.54) ; v1(22.23,60.83) 22.23,61.04 CM21.2 ; CM20.2 22.66,65.1 v1(22.1,65.66) ; C85.1 42.49,73.1 v1(41.91,72.52)
  BOTTOM w0.508: 7.82,41.75 J9.11 ; J9.11 5.79,43.78 ; J9.11 9.85,43.78 ; J9.11 7.82,45.81 ; U13.9 32.26,53.56 ; U13.9 31.63,52.1 ; U13.9 31.63,53.76 ; U13.9 30.8,52.57 ; U13.9 30.8,53.29 ; U13.9 32.45,52.57 ; U13.9 30.99,52.29 ; U13.9 30.8,52.93 ; U13.9 32.26,52.29 ; U13.9 30.99,53.56 ; U13.9 31.27,53.75 ; U13.9 32.46,52.93 ; U13.9 31.27,52.1 ; U13.9 31.99,52.1 ; U13.9 31.99,53.75 ; U13.9 32.45,53.29 ; 12.96,5.26 J81.3 ; J81.3 13.89,6.44 ; J81.3 12.03,6.44 ; J81.3 12.96,7.62 ; U19.10 14.83,54.56 ; U19.10 14.44,54.3 ; U19.10 13.46,54.3 ; U19.10 15.1,55.94 ; U19.10 13.07,56.33 ; U19.10 12.8,54.95 ; U19.10 12.8,55.94 ; U19.10 15.13,55.45 ; U19.10 13.46,56.6 ; U19.10 12.77,55.45 ; U19.10 13.95,56.63 ; U19.10 14.44,56.6 ; U19.10 13.95,54.27 ; U19.10 15.1,54.95 ; U19.10 14.83,56.33 ; U19.10 13.07,54.56 ; U13.16 37.99,55.75 ; U13.16 38.26,54.29 ; U13.16 38.45,54.57 ; U13.16 37.63,54.1 ; U13.16 36.8,54.93 ; U13.16 37.99,54.1 ; U13.16 36.99,55.56 ; U13.16 36.99,54.29 ; U13.16 37.63,55.76 ; U13.16 38.26,55.56 ; U13.16 38.46,54.93 ; U13.16 36.8,54.57 ; U13.16 37.27,55.75 ; U13.16 36.8,55.29 ; U13.16 38.45,55.29 ; U13.16 37.27,54.1 ; U19.15 12.26,69.59 ; U19.15 9.41,70.14 ; U19.15 12.26,68.22 ; U19.15 11.89,67.66 ; U19.15 11.33,70.51 ; U19.15 9.97,67.29 ; U19.15 8.97,68.9 ; U19.15 10.65,67.22 ; U19.15 12.33,68.9 ; U19.15 9.97,70.51 ; U19.15 9.04,69.59 ; 30.8,54.93 U13.10 ; U13.10 32.46,54.93 ; U13.10 31.63,54.1 ; 120.75,9.66 JH1.21 ; JH1.21 122.61,9.66 ; JH1.21 121.68,11.49 ; JH1.21 121.68,7.83 ; 37.63,52.1 U13.15 ; U13.15 38.26,53.56 ; U13.15 38.45,53.29 ; U13.15 37.63,53.76 ; U13.15 37.99,52.1 ; U13.15 36.8,53.29 ; U13.15 38.46,52.93 ; U13.15 38.26,52.29 ; U13.15 36.99,53.56 ; U13.15 36.8,52.57 ; U13.15 37.27,52.1 ; U13.15 37.99,53.75 ; U13.15 37.27,53.75 ; U13.15 36.99,52.29 ; U13.15 38.45,52.57 ; U13.15 36.8,52.93 ; 71.31,78.13 U22.20 72.11,77.33 ; 83.51,75.76 U11.3 82.8,75.99 ; J33.3 73.91,83.68 ; J33.3 73.49,83.66 ; J33.3 73.15,83.44 ; J33.3 74.92,82.68 ; J33.3 73.91,81.67 ; J33.3 74.9,83.1 ; J33.3 74.9,82.25 ; J33.3 74.67,81.92 ; J33.3 72.91,82.68 ; J33.3 72.93,83.1 ; J33.3 74.34,83.66 ; J33.3 74.67,83.44 ; 35.64,30.14 U12.12 35.64,31.79 ; J12.1 112.74,81.91 ; J12.1 111.81,80.98 ; J12.1 111.81,82.84 ; J12.1 110.88,81.91 ; 26.5,78.23 J11.12 ; J11.12 28.36,78.23 ; J11.12 27.43,79.16 ; J11.12 27.43,77.3 ; 62.69,83.66 J56.3 ; J56.3 64.11,82.25 ; J56.3 62.12,82.68 ; J56.3 62.13,83.1 ; J56.3 62.13,82.25 ; J56.3 62.36,83.44 ; J56.3 64.12,82.68 ; J56.3 64.11,83.1 ; J56.3 63.88,83.44 ; J56.3 63.54,83.66 ; J56.3 62.36,81.92 ; J56.3 63.12,83.68 ; J56.3 63.88,81.92 ; 38.82,5.46 39.75,5.46 ; 39.75,5.46 39.75,6.39 ; 39.75,5.46 39.75,4.53 ; 39.75,5.46 40.68,5.46 ; 8.97,53.41 U19.16 ; U19.16 10.65,55.09 ; U19.16 12.33,53.41 ; U19.16 10.65,51.73 ; J36.1 57.4,83.68 ; J36.1 58.41,82.68 ; J36.1 57.4,81.67 ; U12.5 30.47,28.96 ; U12.5 28.81,28.96 ; U12.5 29.64,29.79 ; U12.5 29.64,28.14 ; J12.2 110.24,81.91 ; J12.2 109.31,82.84 ; J12.2 109.31,80.98 ; J12.2 108.38,81.91 ; JH1.23 121.68,5.03 ; JH1.23 122.61,3.7 ; JH1.23 121.68,2.37 ; JH1.23 120.75,3.7 ; J9.5 11.32,33.71 ; J9.5 10.44,34.59 ; J9.5 9.56,33.71 ; J9.5 10.44,32.83 ; 90.42,76.67 U11.10 90.42,78.53 ; J11.13 25.82,80.77 ; J11.13 23.96,80.77 ; J11.13 24.89,79.84 ; J9.1 13.15,34.59 ; J9.1 13.15,32.83 ; J9.1 12.27,33.71 ; J9.1 14.03,33.71 ; 92.46,81.67 J35.1 ; J35.1 93.46,82.68 ; J35.1 91.45,82.68 ; J35.1 92.46,83.68 ; J11.14 24.89,79.16 ; J11.14 24.89,77.3 ; J11.14 23.96,78.23 ; J11.14 25.82,78.23 ; 3.84,73.53 J1.3 ; J1.3 4.67,74.35 ; J1.3 3.01,74.35 ; J1.3 3.84,75.18 ; 17.27,79.84 J11.19 ; J11.19 18.2,80.77 ; J11.19 16.34,80.77 ; 26.5,80.77 J11.11 ; J11.11 28.36,80.77 ; J11.11 27.43,79.84 ; 24.81,28.96 U12.1 ; U12.1 26.47,28.96 ; U12.1 25.64,29.79 ; U12.1 25.64,28.14 ; J81.2 10.16,5.07 ; J81.2 8.98,4.14 ; J81.2 10.16,3.21 ; J81.2 11.34,4.14 ; J9.9 13.5,45.81 ; J9.9 11.47,43.78 ; J9.9 13.5,41.75 ; J9.9 15.53,43.78 ; 106.25,3.7 JH1.22 ; JH1.22 107.18,5.03 ; JH1.22 107.18,2.37 ; JH1.22 108.11,3.7 ; 107.18,7.83 JH1.20 ; JH1.20 106.25,9.66 ; JH1.20 108.11,9.66 ; JH1.20 107.18,11.49 ; 72.11,75.33 U22.19 71.31,74.53 ; 90.42,74.13 U11.9 90.42,75.99 ; 29.97,79.84 J11.9 29.04,80.77 ; 38.82,2.92 39.75,2.92 ; 39.75,2.92 39.75,1.99 ; 39.75,2.92 40.68,2.92 ; 39.75,2.92 39.75,3.85 ; J9.10 13.5,32.67 ; J9.10 11.47,30.64 ; J9.10 15.53,30.64 ; J9.10 13.5,28.61 ; U11.13 95.5,75.99 ; U11.13 96.43,75.06 ; U11.13 95.5,74.13 ; 29.97,77.3 J11.10 ; J11.10 29.04,78.23 ; J11.10 29.97,79.16 ; J11.10 30.9,78.23 ; J9.12 9.85,30.64 ; J9.12 5.79,30.64 ; J9.12 7.82,28.61 ; J9.12 7.82,32.67
  vias: v1(0.48,81.03) v1(0.48,77.22) v1(0.48,73.41) v1(0.48,69.6) v1(0.48,65.79) v1(0.48,61.98) v1(0.48,58.17) v1(0.48,54.36) v1(0.48,50.55) v1(0.48,46.74) v1(0.46,42.65) v1(0.46,38.84) v1(0.46,35.03) v1(0.46,31.22) v1(0.46,27.41) v1(0.46,23.6) v1(0.46,19.79) v1(0.46,15.98) v1(0.46,12.17) v1(0.46,8.36) v1(1.22,49.63) v1(1.37,9.37) v1(1.6,75.67) v1(1.96,21.13) v1(2.06,51.79) v1(2.13,7.47) v1(2.51,59.79) v1(2.46,32.31) v1(2.57,27.74) v1(2.82,33.53) v1(2.79,29.72) v1(3.05,72.92) v1(3.12,43.03) v1(3.3,22.48) v1(3.4,69.93) v1(3.35,16.1) v1(3.35,14.07) v1(3.48,45.8) v1(3.51,37.06) v1(3.51,30.58) v1(3.48,11.71) v1(3.51,9.14) v1(3.56,40.39) v1(3.78,77.06) v1(3.89,19.76) v1(4.19,31.88) v1(4.14,0.48) v1(4.32,50.06) v1(4.5,25.6) v1(4.5,21.87) v1(4.55,84.53) v1(4.62,72.34) v1(4.85,38.02) v1(4.85,29.11) v1(4.95,34.42) v1(5.16,36.37) v1(5.26,60.43) v1(5.28,46.53) v1(5.38,23.42) v1(5.46,76.23) v1(5.49,64.29) v1(5.46,32.72) v1(5.71,62.92) v1(5.66,57.28) v1(5.92,69.09) v1(5.84,9.22) v1(5.97,12.7) v1(6.05,72.21) v1(6.1,13.59) v1(6.22,10.79) v1(6.25,77.5) v1(6.3,24.74) v1(6.5,1.65) v1(6.6,26.8) v1(6.6,12.24) v1(6.63,5.82) v1(6.76,40.13) v1(6.76,14.55) v1(6.91,52.48) v1(6.83,15.98) v1(7.11,25.3) v1(7.24,78.36) v1(7.32,38.35) v1(7.26,9.6) v1(7.39,69.85) v1(7.37,34.54) v1(7.59,36.2) v1(7.59,11.02) v1(7.77,78.36) v1(7.8,59.61) v1(7.9,3.84) v1(7.98,51.59) v1(8,47.62) v1(7.95,0.48) v1(8.1,82.88) v1(8.25,78.94) v1(8.36,84.53) v1(8.38,26.04) v1(8.41,3.02) v1(8.51,63.45) v1(8.53,7.19) v1(8.66,14.4) v1(8.97,78.94) v1(9.12,61.7) v1(9.09,13.03) v1(9.14,26.8) v1(9.37,58.22) v1(9.68,64.62) v1(9.73,45.72) v1(9.83,1.65) v1(9.96,5.82) v1(10.54,29.21) v1(11.15,56.44) v1(11.3,12.7) v1(11.56,72.31) v1(11.66,82.7) v1(11.63,26.44) v1(11.81,49.91) v1(11.73,38.1) v1(11.76,0.48) v1(12.12,61.65) v1(12.09,12.04) v1(12.17,84.53) v1(12.19,64.39) v1(12.19,49.02) v1(12.45,47.5) v1(12.73,59.36) v1(12.65,11.71) v1(13.16,52.45) v1(13.21,12.47) v1(13.23,74.02) v1(13.36,2.18) v1(13.54,67.54) v1(13.59,27.3) v1(13.59,26.67) v1(13.59,26.16) v1(13.72,10.54) v1(13.67,9.98) v1(13.82,76.4) v1(13.77,3.94) v1(13.84,48.08) v1(13.89,14.18) v1(13.84,12.85) v1(13.97,77.6) v1(14.22,27.3) v1(14.22,26.67) v1(14.22,26.16) v1(14.38,69.16) v1(14.45,8.43) v1(14.58,38.84) v1(14.86,9.53) v1(14.99,7.11) v1(15.24,74.17) v1(15.29,47.09) v1(15.32,36.04) v1(15.27,3.56) v1(15.39,78.28) v1(15.37,76.45) v1(15.37,68.83) v1(15.37,49.4) v1(15.37,13.92) v1(15.37,8.38) v1(15.49,11.56) v1(15.49,11.05) v1(15.62,79.38) v1(15.57,0.48) v1(15.65,53.59) v1(15.75,33.15) v1(15.88,29.34) v1(15.98,84.53) v1(16,33.86) v1(16.28,37.06) v1(16.38,39.9) v1(16.33,36.12) v1(16.46,54.89) v1(16.61,13.54) v1(16.69,51.82) v1(16.64,18.64) v1(16.94,45.03) v1(16.99,32.66) v1(17.02,16.13) v1(17.14,31.01) v1(17.42,7.39) v1(17.63,37.21) v1(17.7,51.92) v1(17.68,39.5) v1(17.65,36.14) v1(17.65,12.19) v1(17.65,9.02) v1(17.65,4.24) v1(17.78,73.91) v1(17.8,13.06) v1(17.91,68.45) v1(17.91,59.94) v1(17.88,45.72) v1(18.01,34.04) v1(18.03,70.1) v1(18.21,39.47) v1(18.29,55.93) v1(18.41,73.08) v1(18.49,45.72) v1(18.67,75.95) v1(18.77,69.14) v1(18.82,9.5) v1(18.8,1.52) v1(18.92,79.38) v1(18.92,54.56) v1(18.95,67.87) v1(18.97,48.64) v1(19.05,66.09) v1(19.08,51.97) v1(19.18,70.87) v1(19.18,19.86) v1(19.25,45.62) v1(19.38,0.48) v1(19.46,63.58) v1(19.46,47.04) v1(19.61,61.67) v1(19.63,58.45) v1(19.69,6.83) v1(19.79,84.53) v1(19.81,22.23) v1(19.81,21.72) v1(19.74,18.64) v1(19.76,13.97) v1(19.81,11.43) v1(19.94,20.45) v1(20.19,7.87) v1(20.32,22.23) v1(20.32,21.72) v1(20.32,11.68) v1(20.29,4.24) v1(20.7,73.66) v1(20.95,1.42) v1(21.21,13.59) v1(21.41,55.07) v1(21.46,73.79) v1(21.46,56.9) v1(21.54,56.24) v1(21.62,48.21) v1(21.59,11.3) v1(21.69,52.78) v1(21.64,22) v1(21.81,20.61) v1(21.84,31.37) v1(21.84,30.86) v1(21.84,30.35) v1(21.97,43.81) v1(21.97,12.83) v1(22.05,36.65) v1(22.17,57.35) v1(22.33,9.58) v1(22.35,70.61) v1(22.48,54.23) v1(22.56,44.32) v1(22.61,15.24) v1(22.61,13.59) v1(22.66,4.24) v1(22.73,69.09) v1(22.73,7.37) v1(22.86,57.91) v1(22.99,51.69) v1(23.01,41.71) v1(22.99,18.54) v1(23.06,59.57) v1(23.04,48.74) v1(23.19,0.48) v1(23.24,58.9) v1(23.6,84.53) v1(23.72,14.48) v1(23.89,64.58) v1(23.89,64.02) v1(23.89,63.46) v1(23.89,62.9) v1(23.89,62.34) v1(23.85,19.68) v1(24,56.77) v1(24,12.95) v1(24.05,48.84) v1(24.1,37.72) v1(24.05,36.91) v1(24.21,9.73) v1(24.26,15.62) v1(24.45,64.58) v1(24.45,64.02) v1(24.45,63.46) v1(24.45,62.9) v1(24.45,62.34) v1(24.49,49.33) v1(24.59,57.35) v1(24.77,11.2) v1(24.89,17.78) v1(24.92,12.22) v1(24.89,1.42) v1(25,64.58) v1(25,64.02) v1(25,63.46) v1(25,62.9) v1(25,62.34) v1(24.97,37.8) v1(24.97,19.91) v1(25.4,57.28) v1(25.35,51.77) v1(25.4,47.12) v1(25.53,46.35) v1(25.53,45.47) v1(25.56,64.58) v1(25.56,64.02) v1(25.56,63.46) v1(25.56,62.9) v1(25.56,62.34) v1(25.63,4.19) v1(25.65,57.91) v1(26.12,64.58) v1(26.12,64.02) v1(26.12,63.46) v1(26.12,62.9) v1(26.26,39.19) v1(26.26,38.35) v1(26.29,37.49) v1(26.42,73.41) v1(26.62,12.32) v1(26.67,19.76) v1(26.7,18.03) v1(26.67,15.24) v1(26.67,11.18) v1(27,0.48) v1(27.05,72.54) v1(27.05,44.83) v1(27.18,49.66) v1(27.25,73.05) v1(27.41,84.53) v1(27.56,26.16) v1(27.69,65.74) v1(27.79,8.74) v1(27.81,1.35) v1(28.19,60.33) v1(28.19,59.31) v1(28.55,20.07) v1(28.55,18.92) v1(28.55,17.78) v1(28.78,59.32) v1(29.06,25.6) v1(29.13,37.13) v1(29.13,6.71) v1(29.16,4.09) v1(29.39,65.38) v1(29.46,49.78) v1(29.46,49.02) v1(29.82,34.67) v1(29.97,66.04) v1(30.51,66.04) v1(30.66,1.6) v1(30.81,0.48) v1(30.84,45.59) v1(31.09,6.38) v1(31.22,84.53) v1(31.62,4.17) v1(31.85,7.04) v1(32.26,73.03) v1(32.68,22.84) v1(32.97,46.08) v1(32.99,8.08) v1(33.07,73.05) v1(33.53,68.96) v1(33.55,1.47) v1(33.74,62.75) v1(33.73,21.95) v1(34.04,6.99) v1(34.25,13.32) v1(34.34,18.14) v1(34.62,0.48) v1(35.03,84.53) v1(35.1,75.49) v1(35.18,67.31) v1(35.28,10.41) v1(35.33,25.7) v1(35.43,70.61) v1(35.48,68.83) v1(35.81,61.09) v1(35.74,7.75) v1(35.76,4.8) v1(35.84,25.7) v1(36.04,43.28) v1(36.2,27.81) v1(36.14,1.6) v1(36.45,74.93) v1(36.58,70.87) v1(36.58,13.97) v1(36.58,13.46) v1(36.71,19.6) v1(36.8,49.17) v1(36.96,72.9) v1(37.21,8.03) v1(37.36,10.44) v1(37.59,61.21) v1(37.72,74.9) v1(37.72,71.25) v1(38.07,33.17) v1(38.07,4.17) v1(38.23,74.9) v1(38.33,40.67) v1(38.33,37.19) v1(38.35,35.33) v1(38.43,7.39) v1(38.43,0.48) v1(38.71,44.37) v1(38.71,10.46) v1(38.76,43.15) v1(38.84,84.53) v1(38.86,62.23) v1(38.99,8.33) v1(39.04,70.99) v1(39.12,20.32) v1(39.37,61.34) v1(39.62,10.67) v1(39.8,40.13) v1(39.78,35.31) v1(39.88,42.32) v1(39.9,33.73) v1(39.85,24.66) v1(40,45.49) v1(40.31,71.91) v1(40.31,71.27) v1(40.26,10.67) v1(40.28,8.03) v1(40.46,58.98) v1(40.56,1.42) v1(40.77,10.67) v1(40.89,63.75) v1(41.15,26.29) v1(41.25,20.45) v1(41.4,63.37) v1(41.66,18.92) v1(41.78,62.48) v1(41.91,64.01) v1(41.91,10.79) v1(42.01,3.71) v1(42.04,63.5) v1(42.09,24.13) v1(42.04,6.99) v1(42.04,6.1) v1(42.14,84.53) v1(42.16,49.53) v1(42.16,27) v1(42.27,44.45) v1(42.24,0.48) v1(42.52,43.36) v1(42.62,41.99) v1(42.6,1.52) v1(42.7,20.07) v1(42.93,40.69) v1(43.1,39.34) v1(43.31,61.59) v1(43.28,45.97) v1(43.59,38.2) v1(43.71,59.21) v1(43.66,20.19) v1(43.79,58.14) v1(43.76,3) v1(43.92,37.03) v1(43.87,24.13) v1(43.94,35.56) v1(44.07,64.14) v1(44.09,59.59) v1(44.1,58.54) v1(44.12,34.39) v1(44.12,30.53) v1(44.09,29.29) v1(44.07,28.04) v1(44.2,26.72) v1(44.2,12.73) v1(44.26,25.25) v1(44.32,18.59) v1(44.58,1.04) v1(44.91,1.7) v1(45.01,18.72) v1(45.47,12.55) v1(45.75,3.4) v1(45.95,84.53) v1(45.97,6.1) v1(46.1,6.99) v1(46.05,0.48) v1(46.23,7.92) v1(46.35,45.82) v1(46.35,20.09) v1(46.48,64.14) v1(46.51,40.74) v1(46.48,37.16) v1(46.69,69.98) v1(46.63,24.43) v1(46.74,65.56) v1(46.81,3.07) v1(46.94,10.52) v1(46.94,8.59) v1(47.07,15.52) v1(47.19,12.47) v1(47.14,2.08) v1(47.37,64.14) v1(47.5,14.58) v1(47.62,65.56) v1(47.55,7.47) v1(47.65,4.78) v1(47.78,5.94) v1(48.06,69.97) v1(48.11,39.57) v1(48.08,35.59) v1(48.13,50.67) v1(48.13,46.23) v1(48.13,31.29) v1(48.13,30.1) v1(48.23,1.7) v1(48.39,64.14) v1(48.51,26.54) v1(48.64,83.44) v1(48.64,29.59) v1(48.89,52.37) v1(48.89,28.17) v1(48.87,5.89) v1(49.07,3.4) v1(49.15,11.13) v1(49.28,64.14) v1(49.28,51.18) v1(49.4,13.94) v1(49.5,7.47) v1(49.53,2.26) v1(49.76,84.53) v1(49.73,9.8) v1(49.86,0.48) v1(50.19,52.37) v1(50.14,17.3) v1(50.19,12.04) v1(50.29,81.53) v1(50.27,12.93) v1(50.42,51.18) v1(50.39,29.64) v1(51,83.72) v1(51.1,17.12) v1(51.71,7.85) v1(51.94,52.81) v1(52.12,16.92) v1(52.22,13.46) v1(52.22,11.63) v1(52.5,28.7) v1(52.73,11.69) v1(52.86,51.13) v1(52.98,83.97) v1(52.98,56.85) v1(53.06,13.82) v1(53.09,13.08) v1(53.57,84.53) v1(53.59,20.83) v1(53.57,7.85) v1(53.63,17.05) v1(53.67,0.48) v1(53.92,51.77) v1(53.85,15.93) v1(54.05,57.96) v1(54.1,56.13) v1(54.2,29.64) v1(54.41,54.41) v1(54.86,4.7) v1(54.99,20.57) v1(55.12,58.67) v1(55.3,79.12) v1(55.27,16.84) v1(55.5,17.53) v1(55.47,6.1) v1(55.58,10.59) v1(55.7,7.14) v1(56.01,17.02) v1(56.08,80.24) v1(56.08,52.81) v1(56.26,56.85) v1(56.31,28.7) v1(56.67,51.13) v1(56.77,56.13) v1(56.9,4.72) v1(57.02,16.13) v1(57.02,9.78) v1(57.25,80.29) v1(57.28,64.85) v1(57.38,84.53) v1(57.48,0.48) v1(57.78,79.12) v1(57.73,51.77) v1(57.99,59.79) v1(58.01,29.64) v1(58.12,57.96) v1(58.04,54.41) v1(58.27,4.24) v1(58.5,9.37) v1(58.55,70.87) v1(58.55,15.88) v1(58.85,80.21) v1(59.11,79.1) v1(59.13,83.49) v1(59.18,58.67) v1(59.18,16.48) v1(59.18,14.86) v1(59.18,13.34) v1(59.77,82.25) v1(59.89,52.81) v1(60.12,28.7) v1(60.17,5.61) v1(60.25,80.21) v1(60.32,79.12) v1(60.32,74.73) v1(60.32,15.75) v1(60.4,83.85) v1(60.48,51.13) v1(60.58,14.78) v1(60.58,14.22) v1(60.58,13.67) v1(60.71,64.85) v1(60.83,11.18) v1(60.99,82.91) v1(61.19,84.53) v1(61.29,0.48) v1(61.39,20.62) v1(61.34,9.02) v1(61.44,7.9) v1(61.54,51.77) v1(61.59,4.24) v1(61.82,29.64) v1(61.75,2.82) v1(61.85,54.41) v1(61.98,14.86) v1(61.98,13.34) v1(62.2,56.85) v1(62.28,74.75) v1(62.61,79.12) v1(62.71,56.13) v1(63.2,16.26) v1(63.7,52.81) v1(63.75,16) v1(63.88,66.27) v1(63.93,28.7) v1(63.98,7.26) v1(64.06,57.96) v1(64.03,20.57) v1(64.26,64.85) v1(64.29,51.13) v1(64.34,74.75) v1(64.52,70.1) v1(65,84.53) v1(65.13,58.67) v1(65.1,0.48) v1(65.35,51.77) v1(65.66,70.1) v1(65.66,54.41) v1(65.63,29.64) v1(65.94,17.88) v1(66.42,14.22) v1(66.55,15.88) v1(66.9,82.09) v1(67.16,20.09) v1(67.31,14.48) v1(67.49,56.85) v1(67.51,52.81) v1(67.44,15.49) v1(67.44,11.94) v1(67.74,28.7) v1(67.95,66.27) v1(68,56.13) v1(68.1,51.13) v1(68.07,6.73) v1(68.15,4.37) v1(68.35,20.14) v1(68.81,84.53) v1(68.81,59.64) v1(68.86,9.35) v1(68.91,0.48) v1(68.96,12.06) v1(69.16,51.77) v1(69.34,57.96) v1(69.47,54.41) v1(69.44,29.64) v1(69.6,69.98) v1(69.72,64.85) v1(69.85,20.32) v1(70.05,5.74) v1(70.28,83.34) v1(70.41,58.67) v1(70.66,82.09) v1(70.76,10.72) v1(70.74,9.65) v1(71.32,52.81) v1(71.25,20.32) v1(71.25,14.35) v1(71.37,66.27) v1(71.42,17.25) v1(71.48,4.37) v1(71.55,28.7) v1(71.75,64.85) v1(71.91,51.13) v1(72.19,9.35) v1(72.26,69.98) v1(72.39,74.55) v1(72.52,83.9) v1(72.72,0.48) v1(72.8,56.85) v1(72.85,16.48) v1(72.97,51.77) v1(73.15,11.05) v1(73.3,56.13) v1(73.28,54.41) v1(73.25,29.64) v1(73.46,20.5) v1(73.43,9.42) v1(73.53,69.98) v1(73.53,64.87) v1(73.66,15.37) v1(73.66,13.97) v1(73.79,4.45) v1(73.91,7.11) v1(73.91,2.87) v1(74.12,64.21) v1(74.65,57.96) v1(75.18,84.45) v1(75.18,80.34) v1(75.13,52.81) v1(75.26,75.62) v1(75.27,67.73) v1(75.36,28.7) v1(75.34,10.79) v1(75.69,69.98) v1(75.72,58.67) v1(75.72,51.13) v1(75.82,4.24) v1(76,17.81) v1(76.33,74.55) v1(76.3,20.35) v1(76.43,84.53) v1(76.43,67.79) v1(76.53,0.48) v1(76.68,59.82) v1(76.78,51.77) v1(76.76,9.42) v1(76.83,75.44) v1(76.89,63.58) v1(77.09,54.41) v1(77.06,29.64) v1(77.29,56.85) v1(77.24,2.87) v1(77.34,17.55) v1(77.34,10.92) v1(77.47,4.7) v1(77.57,9.96) v1(77.72,82.17) v1(77.7,72.36) v1(77.72,67.74) v1(77.8,56.13) v1(77.85,74.8) v1(77.98,80.39) v1(77.98,78.99) v1(78.11,64.74) v1(78.23,13.46) v1(78.61,72.36) v1(78.56,69.98) v1(78.74,74.68) v1(78.74,54.41) v1(78.87,20.52) v1(78.94,17.55) v1(79.17,28.7) v1(79.32,59.97) v1(79.27,59.23) v1(79.48,63.37) v1(79.53,51.13) v1(79.48,11.33) v1(79.6,67.74) v1(79.65,84.53) v1(79.76,69.98) v1(80.01,73.15) v1(80.34,0.48) v1(80.64,55.63) v1(80.64,54.48) v1(80.64,17.27) v1(80.75,67.82) v1(80.87,29.64) v1(80.9,9.96) v1(80.9,6.02) v1(81.03,70) v1(81.15,65.18) v1(81.41,17.65) v1(81.41,13.21) v1(81.69,51.66) v1(81.79,54.48) v1(81.89,82.5) v1(82.04,10.92) v1(82.3,17.4) v1(82.35,70.05) v1(82.36,67.88) v1(82.42,4.19) v1(82.55,79.12) v1(82.8,7.39) v1(82.93,82.04) v1(82.98,28.7) v1(82.98,17.32) v1(83.39,82.83) v1(83.34,51.13) v1(83.46,84.53) v1(83.82,66.62) v1(83.82,17.14) v1(83.9,17.86) v1(83.95,13.34) v1(84.23,6.02) v1(84.15,0.48) v1(84.33,79.12) v1(84.33,10.92) v1(84.44,61.89) v1(84.58,17.2) v1(84.68,29.64) v1(84.66,17.88) v1(84.79,23.75) v1(85.09,51.18) v1(85.34,17.78) v1(85.47,29.57) v1(85.6,50.55) v1(85.56,47.52) v1(85.6,41.88) v1(85.6,37.47) v1(85.62,32.77) v1(85.6,30.1) v1(85.88,56.39) v1(86.06,22.68) v1(86.21,60.2) v1(86.39,65.1) v1(86.33,63.98) v1(86.36,17.78) v1(86.44,75.41) v1(86.46,63.2) v1(86.49,53.21) v1(86.64,22.66) v1(86.87,66.01) v1(86.87,61.26) v1(86.89,30.84) v1(86.94,62.07) v1(87.07,10.46) v1(87.12,2.92) v1(87.2,28.47) v1(87.27,84.53) v1(87.25,17.78) v1(87.63,58.14) v1(87.63,54.23) v1(87.58,23.83) v1(87.91,9.35) v1(87.91,5.36) v1(88.01,17.78) v1(87.96,0.48) v1(88.06,20.17) v1(88.21,65.1) v1(88.18,62.08) v1(88.18,61.22) v1(88.24,63.98) v1(88.49,63.2) v1(88.65,82.3) v1(89.03,4.29) v1(89.13,20.19) v1(89.18,55.09) v1(89.28,48.06) v1(89.26,43.97) v1(89.28,35.38) v1(89.33,56.46) v1(89.61,63.98) v1(89.71,65.1) v1(89.64,62.08) v1(89.66,61.24) v1(89.66,60.2) v1(89.81,10.72) v1(89.81,6.73) v1(89.92,69.98) v1(89.84,55.91) v1(89.92,15.49) v1(90.09,47.52) v1(90.17,22.61) v1(90.3,12.57) v1(90.4,46.56) v1(90.42,45.21) v1(90.37,41.63) v1(90.5,40.31) v1(90.45,37.06) v1(90.47,35.48) v1(90.45,2.92) v1(90.55,43.92) v1(90.7,29.62) v1(91.08,84.53) v1(91.26,63.98) v1(91.31,63.2) v1(91.33,58.82) v1(91.24,9.35) v1(91.24,5.36) v1(91.41,69.95) v1(91.57,54.74) v1(91.69,56.77) v1(91.64,20.14) v1(91.72,7.26) v1(91.74,53.72) v1(91.74,17.93) v1(91.77,0.48) v1(91.85,55.65) v1(92.23,66.19) v1(92.2,48.31) v1(92.33,10.64) v1(92.51,60.53) v1(92.46,50.39) v1(92.51,17.86) v1(92.56,49.81) v1(92.63,64.92) v1(92.68,46.28) v1(92.66,42.27) v1(92.81,45.01) v1(92.74,43.79) v1(92.84,57.4) v1(92.86,52.63) v1(92.95,21.58) v1(93.27,61.06) v1(93.34,64.26) v1(93.73,14.86) v1(93.9,61.85) v1(94.11,36.4) v1(94.08,33.22) v1(94.06,31.01) v1(94.06,23.14) v1(94.61,81.92) v1(94.59,8.69) v1(94.59,6.86) v1(94.89,84.53) v1(95.02,11.05) v1(95.12,81.92) v1(95.3,16.38) v1(95.38,14.35) v1(95.58,0.48) v1(95.71,15.27) v1(96.09,4.62) v1(96.19,13.69) v1(96.22,10.31) v1(96.32,70.08) v1(96.32,41.83) v1(96.39,64.64) v1(96.42,62.84) v1(96.37,55.96) v1(96.39,55.32) v1(96.39,49.56) v1(96.39,47.07) v1(96.37,44.55) v1(96.34,30.78) v1(96.34,8.64) v1(96.44,66.45) v1(96.44,60.4) v1(96.47,58.78) v1(96.44,41.25) v1(96.52,27.94) v1(96.49,21.84) v1(96.6,52.25) v1(96.55,35.43) v1(96.8,32.64) v1(96.85,54.18) v1(96.9,19.56) v1(96.85,13.03) v1(97.03,39.42) v1(97.1,51.71) v1(97.16,73.79) v1(97.21,41.35) v1(97.51,3.25) v1(97.61,46.13) v1(97.54,14.86) v1(97.54,11.1) v1(97.54,10.31) v1(97.69,34.52) v1(97.82,53.77) v1(97.89,80.98) v1(97.92,80.34) v1(97.87,31.8) v1(97.99,23.11) v1(98.09,64.36) v1(98.04,61.9) v1(98.04,56.74) v1(98.12,20.6) v1(98.17,18.03) v1(98.27,57.66) v1(98.25,14.15) v1(98.25,7.34) v1(98.42,81.66) v1(98.48,35.66) v1(98.48,1.93) v1(98.7,84.53) v1(98.68,75.82) v1(98.81,63.5) v1(98.76,49.81) v1(98.76,23.9) v1(98.91,47.22) v1(98.98,77.44) v1(98.96,55.32) v1(98.93,41.43) v1(98.96,38.13) v1(99.06,71.88) v1(99.11,40.46) v1(99.11,33.15) v1(99.06,22.1) v1(99.11,19.61) v1(99.19,42.75) v1(99.42,4.62) v1(99.39,0.48) v1(99.44,81.31) v1(99.52,37.13) v1(99.44,13.16) v1(99.62,83.16) v1(99.82,52.37) v1(99.75,39.4) v1(99.77,34.39) v1(99.85,18.41) v1(99.87,13.89) v1(99.95,24.26) v1(99.97,12.62) v1(100.33,10.97) v1(100.41,2.64) v1(100.43,36.58) v1(100.46,7.24) v1(100.51,5.64) v1(100.71,20.57) v1(100.63,13.67) v1(100.81,48.18) v1(100.79,35.43) v1(100.81,10.46) v1(100.86,78.94) v1(100.84,75.51) v1(100.84,19.3) v1(100.84,3.25) v1(101.02,83.26) v1(100.97,77.67) v1(100.94,24.85) v1(101.17,80.04) v1(101.17,71.91) v1(101.22,69.57) v1(101.27,36.78) v1(101.32,36.14) v1(101.4,63.75) v1(101.5,34.47) v1(101.47,13.59) v1(101.6,12.88) v1(101.73,23.62) v1(101.78,33.07) v1(101.8,1.93) v1(101.88,50.5) v1(101.85,27.94) v1(101.96,42.11) v1(101.98,37.59) v1(101.93,18.26) v1(102.39,60.12) v1(102.51,84.53) v1(102.54,48.79) v1(102.59,38.25) v1(102.72,72.09) v1(102.72,70.89) v1(102.74,15.11) v1(102.74,14.48) v1(102.77,10.97) v1(102.87,39.93) v1(103,58.93) v1(103.02,42.04) v1(103,13.08) v1(103.12,57.66) v1(103.17,56.74) v1(103.2,0.48) v1(103.25,9.91) v1(103.28,7.26) v1(103.43,78.03) v1(103.45,79.5) v1(103.61,76) v1(103.53,49.15) v1(103.66,83.54) v1(103.63,12.57) v1(103.76,73.3) v1(103.86,63.78) v1(104.01,66.62) v1(103.96,60.6) v1(104.01,4.52) v1(104.06,69.95) v1(104.14,19.3) v1(104.17,8.28) v1(104.42,76.94) v1(104.47,39.85) v1(104.52,13.06) v1(104.52,10.41) v1(104.67,9.12) v1(105.03,55.12) v1(105.08,79.2) v1(105.08,39.85) v1(105.08,5.54) v1(105.16,26.54) v1(105.13,14.1) v1(105.16,11.18) v1(105.31,33.22) v1(105.28,27.43) v1(105.28,16.89) v1(105.41,7.04) v1(105.66,56.77) v1(105.66,30.12) v1(105.71,12.7) v1(105.79,32.87) v1(105.94,34.32) v1(106.05,54.46) v1(106.05,19.56) v1(106.22,43.41) v1(106.32,84.53) v1(106.3,56.77) v1(106.43,77.72) v1(106.35,47.57) v1(106.4,45.48) v1(106.35,44.45) v1(106.53,48.62) v1(106.48,46.53) v1(106.55,20.7) v1(106.65,34.34) v1(106.81,30.23) v1(106.91,54.58) v1(107.01,0.48) v1(107.06,79.91) v1(107.06,12.45) v1(107.31,53.19) v1(107.31,23.62) v1(107.39,83.54) v1(107.39,41.78) v1(107.44,25.91) v1(107.54,34.59) v1(107.65,76.94) v1(107.82,20.7) v1(107.87,33.83) v1(108.03,40.39) v1(108.08,28.83) v1(108.23,6.32) v1(108.33,54.91) v1(108.36,54.41) v1(108.38,52.2) v1(108.38,51.66) v1(108.33,30.23) v1(108.61,33.02) v1(108.69,48.62) v1(108.79,78.71) v1(108.74,7.04) v1(108.86,41.96) v1(108.99,10.21) v1(108.97,8.18) v1(109.22,28.07) v1(109.4,54) v1(109.4,53.39) v1(109.42,52.83) v1(109.37,34.06) v1(109.47,3.23) v1(109.6,5.08) v1(109.73,39.37) v1(109.73,30.23) v1(109.75,77.57) v1(109.8,1.98) v1(109.86,19.56) v1(109.98,33.15) v1(110.13,84.53) v1(110.24,60.58) v1(110.31,58.98) v1(110.24,23.62) v1(110.36,29.08) v1(110.49,79.55) v1(110.59,47.52) v1(110.57,47.02) v1(110.59,33.83) v1(110.74,28.57) v1(110.82,0.48) v1(110.85,40.03) v1(110.87,26.8) v1(110.87,8.64) v1(111.02,7.19) v1(111.3,4.34) v1(111.4,77.67) v1(111.52,60.15) v1(111.63,34.04) v1(111.63,25.91) v1(111.76,30.23) v1(111.76,24.38) v1(112.04,80.14) v1(112.12,45.77) v1(112.22,33.1) v1(112.32,47.45) v1(112.29,46.84) v1(112.39,29.08) v1(112.37,12.75) v1(112.65,8) v1(112.83,34.29) v1(112.78,30.23) v1(112.8,3.23) v1(112.93,45.26) v1(112.93,5.08) v1(112.95,79.32) v1(112.95,6.38) v1(113.13,1.98) v1(113.28,23.75) v1(113.41,32.92) v1(113.41,28.32) v1(113.36,12.73) v1(113.44,33.6) v1(113.66,30.23) v1(113.79,55.83) v1(113.82,34.11) v1(113.79,27.18) v1(113.87,76.73) v1(113.94,84.53) v1(114.3,58.55) v1(114.27,54.03) v1(114.33,47.65) v1(114.33,46.94) v1(114.3,22.86) v1(114.35,7.19) v1(114.53,52.96) v1(114.6,53.54) v1(114.6,34.06) v1(114.55,21.72) v1(114.68,30.23) v1(114.63,4.34) v1(114.63,0.48) v1(114.78,54.94) v1(114.81,33.27) v1(114.99,82.47) v1(114.96,60.35) v1(115.19,80.42) v1(115.16,2.92) v1(115.39,5.16) v1(115.65,60.35) v1(115.75,77.22) v1(115.82,58.55) v1(116.03,78.84) v1(115.98,78.05) v1(116.1,79.6) v1(116.31,45.03) v1(116.28,6.38) v1(116.38,58.57) v1(116.33,14.35) v1(116.46,12.45) v1(116.71,81.23) v1(116.64,77.83) v1(116.79,1.7) v1(116.92,79.53) v1(116.89,7.39) v1(116.94,58.55) v1(117.04,47.12) v1(117.04,46.43) v1(117.07,4.62) v1(117.17,77.8) v1(117.27,56.01) v1(117.25,40.51) v1(117.58,41.76) v1(117.63,20.9) v1(117.6,20.22) v1(117.6,19.56) v1(117.65,60.45) v1(117.73,22.1) v1(118.01,21.41) v1(117.98,18.67) v1(117.96,0.48) v1(118.29,7.11) v1(118.34,42.55) v1(118.36,22.23) v1(118.36,20.57) v1(118.49,2.92) v1(118.57,45.77) v1(118.54,45.14) v1(118.62,19.56) v1(118.72,5.16) v1(118.82,46.61) v1(118.8,21.36) v1(119,20.57) v1(119.05,63.35) v1(119.05,60.45) v1(119.05,44.78) v1(119.2,84.53) v1(119.18,58.45) v1(119.15,54.05) v1(119.23,6.45) v1(119.28,56.06) v1(119.37,50.67) v1(119.58,65.13) v1(119.53,46.56) v1(119.63,69.29) v1(119.74,43.87) v1(119.76,21.59) v1(119.76,16.13) v1(119.76,11.56) v1(119.91,37.82) v1(119.96,39.42) v1(119.96,10.57) v1(120.12,1.7) v1(120.2,35.69) v1(120.14,16.89) v1(120.22,7.39) v1(120.19,5.64) v1(120.42,67.16) v1(120.47,29.54) v1(120.57,28.14) v1(120.7,40.18) v1(120.65,33.66) v1(120.9,33.15) v1(120.9,32.13) v1(121.08,38.37) v1(121.03,30.86) v1(121.23,29.08) v1(121.39,58.47) v1(121.41,35.43) v1(121.59,28.14) v1(121.67,70.21) v1(121.67,62.36) v1(121.79,72.19) v1(121.74,17.53) v1(122,57.25) v1(122.1,67.77) v1(122.05,60.71) v1(122.05,16.26) v1(122.3,31.09) v1(122.33,25.27) v1(122.33,0.51) v1(122.45,20.57) v1(122.55,6.45) v1(122.63,51.51) v1(122.78,40.97) v1(122.81,35.05) v1(122.76,33.5) v1(122.83,49.61) v1(122.83,49.07) v1(122.86,36.6) v1(122.96,41.48) v1(122.94,22.35) v1(122.96,1.47) v1(123.19,58.17) v1(123.22,56.26) v1(123.19,11.43) v1(123.24,32.92) v1(123.44,54.23) v1(123.44,16.92) v1(123.6,84.51) v1(123.67,13.92) v1(123.9,63.14) v1(123.93,59.39) v1(124.13,69.27) v1(124.08,64.77) v1(124.28,78.05) v1(124.26,74.22) v1(124.33,72.42) v1(124.43,71.58) v1(124.51,19.05) v1(124.61,67.79) v1(124.64,27) v1(124.74,33.3) v1(124.92,75.72) v1(124.94,61.37) v1(125.02,31.72) v1(124.97,23.04) v1(124.99,20.62) v1(124.94,10.74) v1(125.12,58.22) v1(125.43,66.32) v1(125.37,13.77) v1(125.53,16.87) v1(125.55,72.31) v1(125.6,0.56) v1(125.68,24.03) v1(125.73,61.47) v1(125.83,32.59) v1(125.93,59.46) v1(125.96,39.62) v1(125.98,27.18) v1(126.06,53.95) v1(126.11,38.1) v1(126.11,36.37) v1(126.14,58.57) v1(126.14,56.26) v1(126.29,21.44) v1(126.42,60.25) v1(126.49,69.49) v1(126.49,68) v1(126.49,61.9) v1(126.49,44.09) v1(126.54,70.84) v1(126.54,65.79) v1(126.57,64.06) v1(126.62,11.3) v1(126.7,15.98) v1(126.85,30.35) v1(127,75.74) v1(127.05,17.37) v1(127.41,55.98) v1(127.51,29.21) v1(127.64,38.07) v1(127.64,36.17) v1(127.64,34.52) v1(127.97,32.41) v1(128.12,72.19) v1(128.04,31.47) v1(128.22,57.78) v1(128.3,56.34) v1(128.37,69.62) v1(128.37,67.84) v1(128.4,64.31) v1(128.42,59.08) v1(128.47,77.01) v1(128.45,75.69) v1(128.45,62.08) v1(128.5,52.43) v1(128.47,48.13) v1(128.5,42.65) v1(128.73,44.73) v1(129.16,66.29) v1(129.21,63.2) v1(129.26,60.4) v1(129.25,36.36) v1(129.39,34.52) v1(129.46,41.96) v1(129.44,38.15) v1(129.59,80.8) v1(129.59,76.99) v1(129.59,73.18) v1(129.59,69.37) v1(129.59,65.56) v1(129.59,61.75) v1(129.59,57.94) v1(129.59,54.13) v1(129.59,50.32) v1(129.59,46.51) v1(129.57,43.59) v1(129.57,39.78) v1(129.57,35.97) v1(129.57,32.16) v1(129.57,28.35) v1(129.57,24.54) v1(129.57,20.73) v1(129.57,16.92) v1(129.57,13.11) v1(129.57,9.3) v1(129.57,6.25) v2(9.02,19.96) v2(9.14,18.29) v2(9.14,17.53)
